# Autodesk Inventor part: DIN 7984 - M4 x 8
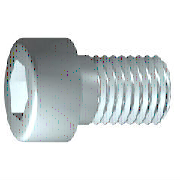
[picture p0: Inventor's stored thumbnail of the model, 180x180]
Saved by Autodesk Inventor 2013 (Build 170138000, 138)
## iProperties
IsCustomPart: 0
Created: 2012-02
Part Number: DIN 7984 - M4 x 8
Material: Stahl, weich
Description: Zylinderkopfschraube
Document SubType Name: Modeling
Standard: DIN 7984
Designer: rYan
Standard Revision: 1985
Standards Organization: DIN
Language: de-DE
Size Designation: M4 x 8
Categories: <MemberInstance><Categories><Category DisplayName="Verbindungselemente" InternalName="e4da775c-781d-43d5-af7c-5136215cf5a6" Mnemonic="FSTN"><Category DisplayNam
Density: 7.86 g/cm^3
Mass: 1.51137 g
Surface Area: 2.52684 cm^2
Volume: 0.192286 cm^3
Author: rYan
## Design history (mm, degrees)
sketch "Skizze1"
  geometry: L1 (0.333, 0)-(8, 0); L2 (8, 0)-(8, 2); L3 (8, 2)-(2.1, 2); L4 (2.1, 2)-(1.67, 2); L5 (1.67, 2)-(0, 2); L6 (0, 2)-(0, 3.5); L7 (0, 3.5)-(-2.8, 3.5); L8 (-2.8, 3.5)-(-2.8, 1.443); L9 (-2.8, 1.443)-(-0.5, 1.443); L10 (-0.5, 1.443)-(0.333, 0); L11 (-4.96, 0)-(10.16, 0) reference; L12 (0, -0.7)-(0, 4.2) reference; L13 (2.1, 2)-(0, 2)
  constraints: 22 end point, 6 parallel, 2 collinear, 2 perpendicular, 1 horizontal, 1 point on line
  dimensions: "d1" = 5.9 distance from line of L3.end L2 (= GEL); "d2" = 0.42952 distance of L4.end L3.end (computed from GAL); "d3" = 2.8 distance between parallel lines of L8 L6 (= KOH); "d4" = 2.3 distance of L8.end L9.end (= INTI); "d5" = 60 deg angle of L10 L1; "d6" = 4 diameter of L3 L1 (= GD); "d7" = 4 diameter of L5 L1 (= BDM); "d8" = 2.88675 diameter of L9 L1 (= 1.1547 x SW); "d9" = 7 diameter of L7 L1 (= KOD); "d26" = 8 distance between parallel lines of L12 L2 (= NLG)
revolve "Körper" sketch "Skizze1" stored, may be unused: angle "d10" = 90 deg
sketch "Skizze2"
  geometry: L1 (0, -4.9)-(0, 4.9) reference; L2 (-4.9, 0)-(4.9, 0) reference; L3 (1.443, 0)-(0.722, -1.25); L4 (0.722, -1.25)-(-0.722, -1.25); L5 (-0.722, -1.25)-(-1.443, 0); L6 (-1.443, 0)-(-0.722, 1.25); L7 (-0.722, 1.25)-(0.722, 1.25); L8 (0.722, 1.25)-(1.443, 0); 2 further points
  constraints: 12 end point, 1 coincident, 1 horizontal alignment, 1 point on line, 12 other
extrude "Loch" join sketch "Skizze2" stored distance "d11" = 10; taper "d12" = 0 deg
workplane "Work Plane1"
fillet "Fillet2" dims "d30" = 0.1 (= R)
body "Solid1"
fillet "Rundung1" dims "d17" = 0.4 (= RR)
feature "Gewinde" dims "d13" = 5.9 (= GEL), "d14" = 0
chamfer "Fase1" distance "d15" = 0.42941 (= -0.5 x SPD + 0.5 x GD); stored, may be unused: second distance "d16" = 0.42941 (= GUL), angle "d27" = 45 deg
other parameters: "GD" = 4 (= NND) [user parameter; used in 2 equation terms], "NLG" = 8 [user parameter; used in 1 equation term], "GEL" = 5.9 [user parameter; used in 2 equation terms], "KOD" = 7 [user parameter; used in 1 equation term], "KOH" = 2.8 [user parameter; used in 1 equation term], "INTI" = 2.3 [user parameter; used in 1 equation term], "GAL" = 0.42941 (= 0.61345 x PTC) [user parameter; used in 1 equation term], "GUL" = 0.42941 (= 0.61345 x PTC) [user parameter; used in 1 equation term], "BDM" = 4 (= NND) [user parameter; used in 1 equation term], "SW" = 2.5 [user parameter; used in 2 equation terms], "RR" = 0.4 [user parameter; used in 1 equation term], "SPD" = 3.14117 (= NND - 1.2269 x PTC) [user parameter; used in 1 equation term], "d19" = 0, "d28" = 0, "d29" = 0, "R" = 0.1 [user parameter; used in 1 equation term], "TOA" = 30 deg [user parameter], "GD1" = 3.14117 (= THREADDIA - 1.2269 x PTC) [user parameter], "THREADDIA" = 4 [user parameter; used in 1 equation term], "FAWI" = 45 deg [user parameter], "ANG" = 120 deg [user parameter], "TPU" = 14.28571 (computed from PTC) [user parameter], "PTC" = 0.7 [user parameter; used in 5 equation terms], "NND" = 4 [user parameter; used in 3 equation terms], "E0" = 2.8875 (= 1.155 x SW) [user parameter]
